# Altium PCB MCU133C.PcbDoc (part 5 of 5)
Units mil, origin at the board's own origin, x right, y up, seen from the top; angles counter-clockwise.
Board outline 2300 x 5500 mil, 4 copper layers (Top Signal, GND, PWR, Bottom Signal), stack 61.6 mil thick; 278 components, 226 nets, 1057 pads, 868 vias.
Unrouted connection lines stored in the file: 237.
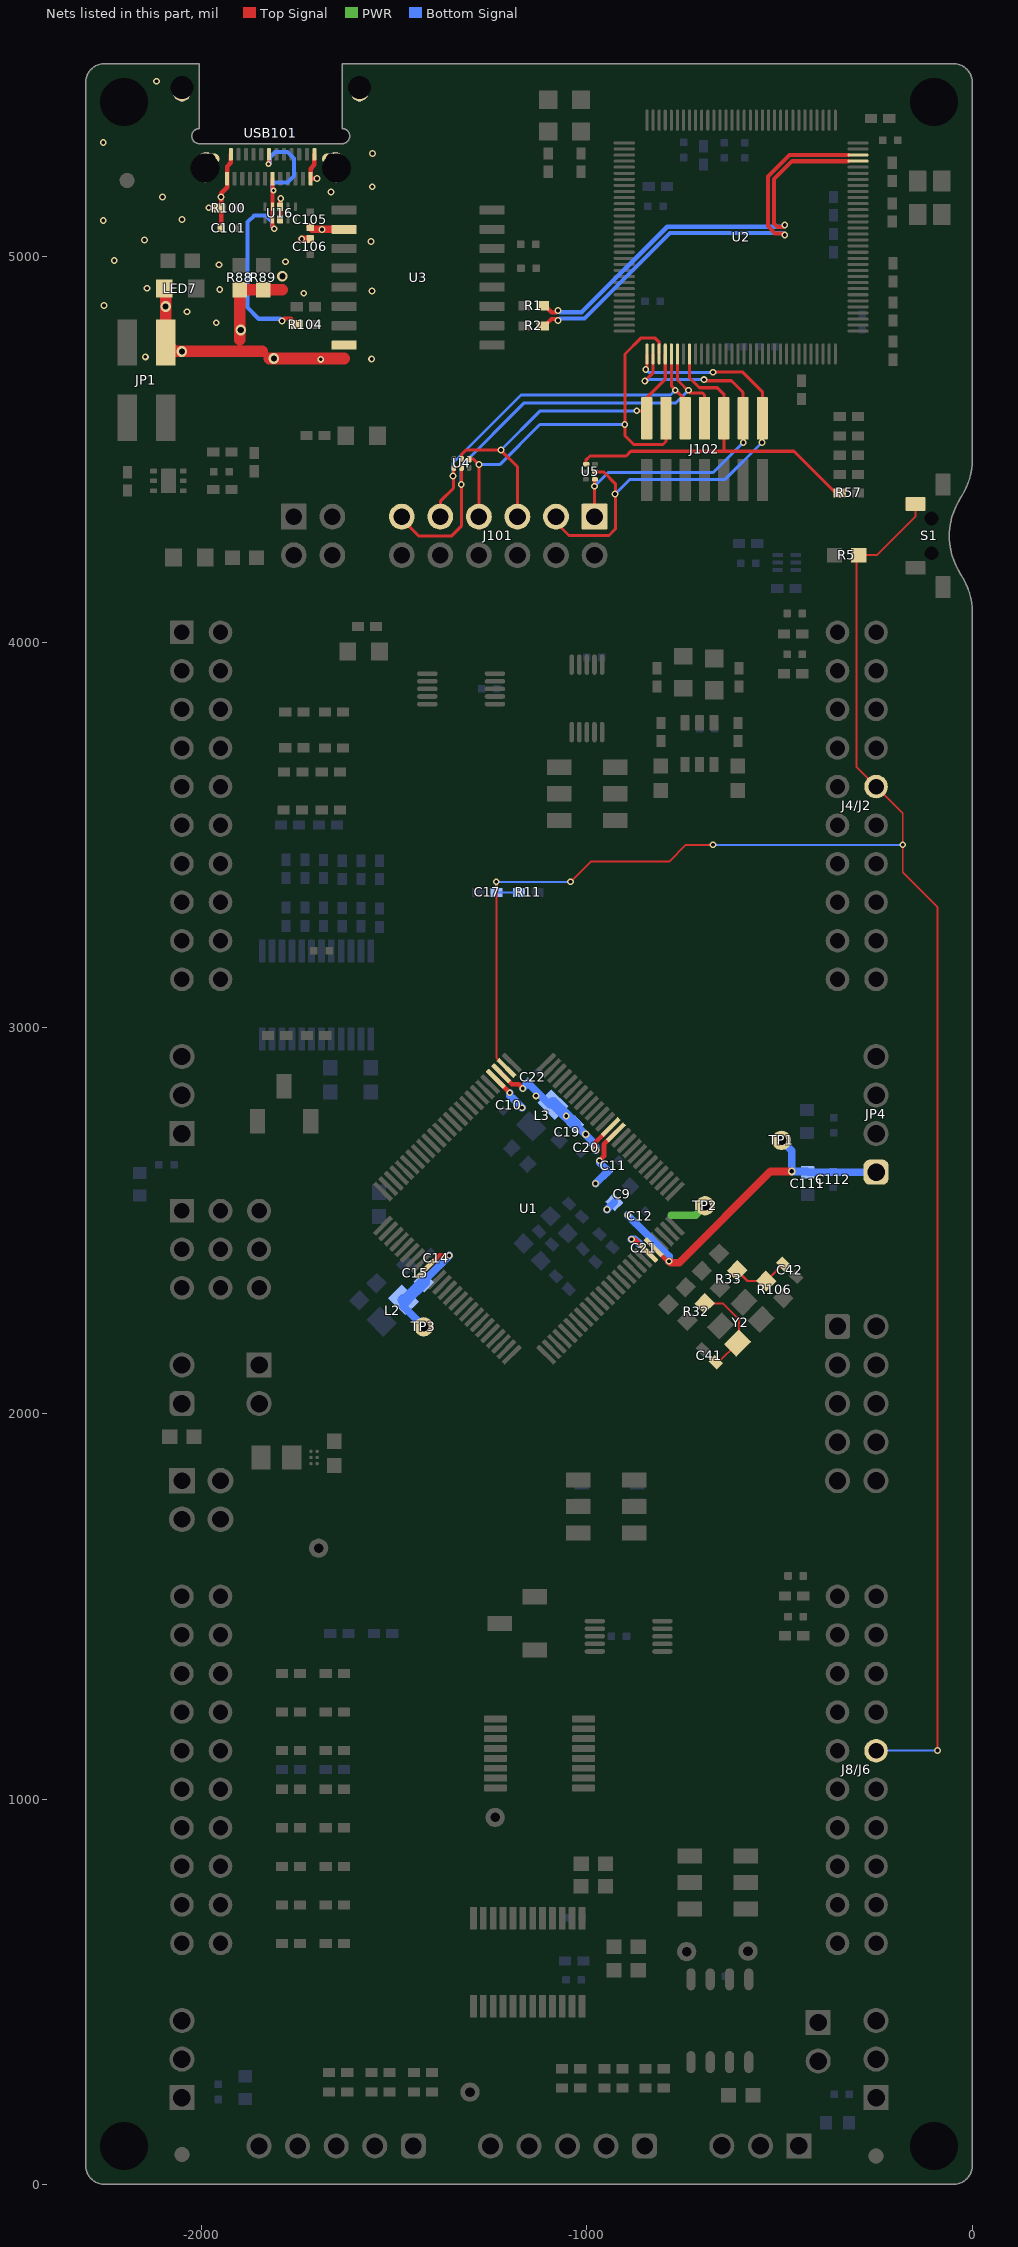
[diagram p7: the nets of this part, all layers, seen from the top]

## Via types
v1: diameter 17.72, hole 9.84, Top Signal to Bottom Signal, tented both sides, 822 vias
v2: diameter 19.68, hole 11.81, Top Signal to Bottom Signal, tented both sides, 22 vias
v3: diameter 27.56, hole 15.75, Top Signal to Bottom Signal, tented both sides, 17 vias
v4: diameter 15.75, hole 7.87, Top Signal to Bottom Signal, tented both sides, 5 vias
v5: diameter 19.68, hole 7.87, Top Signal to Bottom Signal, tented both sides, 2 vias

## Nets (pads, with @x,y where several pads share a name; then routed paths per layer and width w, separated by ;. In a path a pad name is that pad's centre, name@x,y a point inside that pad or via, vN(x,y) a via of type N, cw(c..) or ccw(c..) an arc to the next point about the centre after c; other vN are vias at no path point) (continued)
USB_D_P: R104.1 U16.2 U16.9 USB101.A6 USB101.B6 | length 849.1
  Top Signal w7.87: v4(-1825.43,5239.8) v4@-1824.65,5240.59
  Top Signal w10.63: v4@-1824.65,5240.59 USB101.B6@-1824.65,5265.12 ; USB101.A6@-1814.8,5202.13 -1814.8,5171.54 -1814.8,5076.3 v1(-1810.51,5072.01) ; v1(-1790.71,4833.23) -1784.86,4839.07 -1767.85,4839.07 R104.1@-1752.2,4823.43
  Bottom Signal w10.63: v4(-1825.43,5239.8) -1822.09,5243.15 -1822.09,5256.97 -1808.11,5270.94 -1776.18,5270.94 -1759.29,5254.05 -1759.29,5208.62 -1776.3,5191.61 -1808.94,5191.61 -1816.65,5183.9 -1816.65,5175.51 v4(-1812.68,5171.54) ; v1(-1810.51,5072.01) -1816.32,5077.82 -1816.32,5089.62 -1833.39,5106.69 -1862.44,5106.69 -1879.92,5089.21 -1879.92,4867.72 -1850.91,4838.7 -1796.18,4838.7 v1(-1790.71,4833.23)
USB_GND: C101.1 C105.1 C106.1 JP1.3 LED7.1 R88.1 R89.1 R100.1 U3.2 U3.8 U16.3@-1795.2,5096.4 U16.8@-1795.2,5129.27 USB101.1 USB101.2 USB101.3 USB101.4 USB101.A1 USB101.A12 USB101.B1 USB101.B12 | length 1317.6
  Top Signal w11.81: v1(-1980.55,5126.73) -1953.46,5126.73 R100.1@-1952.28,5125.55 ; C101.1@-1948.43,5073.35 -1948.43,5164.61 -1932.91,5180.12 USB101.A12@-1932.91,5202.13 -1932.91,5233.58 -1923.07,5243.43 USB101.B1@-1923.07,5265.12 ; U16.8@-1795.2,5132.38 -1794.37,5133.21 U16.8@-1795,5133.84 ; U16.3@-1795,5098.84 v1@-1795,5150.39 ; C106.1@-1718.24,5045.35 C106.1@-1716.04,5047.55 ; USB101.B12@-1706.54,5265.12 -1706.54,5237.99 -1716.38,5228.15 USB101.A1@-1716.38,5202.13 v1(-1699.41,5202.13)
  Top Signal w19.68: v1(-1739.31,5045.35) C106.1@-1718.24,5045.35 ; C105.1@-1717.44,5075.67 -1712.32,5070.55 U3.2@-1629.53,5070.55
  Top Signal w30: LED7.1@-2092.01,4919.41 JP1.3@-2092.01,4776.99 -2069.31,4754.29 -1930.04,4754.29 -1842.09,4754.29 ; -1899.66,4784.67 R88.1@-1899.66,4913.94 R89.1@-1838.7,4913.94 -1789.8,4913.94 ; v3@-1823.35,4735.55 -1629.53,4735.55
  other v1: -1690.16,4733.46 -1558.03,4734.49 -2144.92,4739.92 -1961.18,4828.27 -2037.01,4856.97 -2251.85,4873.07 -1734.21,4904.65 -1557.52,4910.67 -1952.01,4914.45 -2140.35,4917.8 -1954.29,4978.78 -1781.54,4986.55 -2225.55,4989.61 -1559.61,5039.13 -2147.32,5043.11 -1686.5,5069.88 -2254.17,5093.66 -2049.65,5095.94 -1793.58,5150.39 -2100.2,5154.57 -1948.9,5154.45 -1663.43,5167.76 -1556.46,5181.18 -1555.63,5267.17 -2254.17,5295.87 -2116.3,5454.41
  other v3: -1811.57,4735.47 -2050.2,4753.74 -1897.48,4809.45 -2092.17,4870.63 -1789.8,4948.94
VDD: C9.2 C10.2 C11.2 C12.2 C111.2 C112.2 JP4.1 TP1.1 U1.4 U1.71 U1.87 | length 1252.7
  Top Signal w11.81: U1.4@-1236.36,2867.95 -1200.04,2831.63 v1(-1200.04,2831.55) v1@-1202.6,2831.55 ; U1.71@-827.13,2430.88 -790.94,2394.69 v1(-787.04,2394.69)
  Top Signal w12: v1(-966.92,2655.21) -955.69,2666.44 -955.69,2697.63 U1.87@-924.56,2728.76
  Top Signal w19.68: v1(-787.04,2394.69) -782.82,2390.47 -760.81,2390.47 -523.8,2627.48 v2(-468.54,2627.48)
  Bottom Signal w19.68: v1(-1200.04,2831.55) -1200.04,2824.22 C10.2@-1188.79,2812.97 ; C10.2@-1188.71,2813.06 v1@-1168.12,2792.47 ; v1(-977.46,2596.32) C11.2@-945.16,2628.61 -966.92,2650.38 v1(-966.92,2655.21) ; v1(-947.83,2528.53) -947.83,2528.7 C9.2@-928.74,2547.79 ; v1@-893.94,2515.67 v1(-893.94,2514.28) C12.2@-876.54,2496.88 -787.04,2407.38 v1(-787.04,2394.69) ; TP1.1@-495.04,2708.05 -468.54,2681.56 v2(-468.54,2627.48) C111.2@-429.6,2627.48 ; C111.2@-427.54,2625.43 -427.41,2625.55 C112.2@-361.04,2625.55 JP4.1@-250.04,2625.55
  other v1: -1168.04,2792.55
VDDA: C14.2 C15.1 L2.2 TP3.1 U1.34 | length 334.2
  Top Signal w11.81: U1.34@-1417.31,2375.2 -1382.96,2409.55 v1(-1356.72,2409.55)
  Bottom Signal w19.68: L2.2@-1475.38,2294.55 -1475.38,2276.88 TP3.1@-1423.05,2224.55 ; C15.1@-1422.93,2340.95 -1422.93,2343.3 -1389.39,2376.85 v1(-1356.72,2409.55)
  Bottom Signal w31.5: L2.2@-1475.38,2294.55 -1469.34,2294.55 C15.1@-1422.93,2340.95
VDDIO: C19.2 C20.2 C21.2 C22.2 L3.2 TP2.1 U1.3 U1.70 U1.88 | length 610.2
  Top Signal w11.81: U1.3@-1222.44,2881.87 -1194.12,2853.55 -1176.69,2853.55 v1(-1166.04,2842.9) ; v1(-976.46,2682.79) -976.46,2704.7 U1.88@-938.48,2742.68 ; v1(-884.22,2451.55) -875.64,2451.55 U1.70@-841.05,2416.96
  PWR w19.68: -781.04,2513.53 -718.38,2513.53 -697.04,2534.87 TP2.1@-697.04,2544.55
  Bottom Signal w19.68: v1(-1166.04,2842.9) -1153.72,2855.22 C22.2@-1153.72,2858.05 -1096.5,2800.84 L3.2@-1087.75,2800.84 ; C19.2@-1030.23,2749.93 -987.69,2707.39 C20.2@-987.69,2702.47 -976.46,2691.24 v1(-976.46,2682.79) ; v1(-884.22,2451.55) -875.64,2451.55 C21.2@-865.96,2441.87
  Bottom Signal w30: L3.2@-1087.75,2806.06 v1(-1053.25,2771.55) C19.2@-1030.23,2749.93
  other v1: -1132.04,2823.55
  other v2: -1003.04,2723.55
XDS_D_N: R1.2 U2.93 | length 1103.7
  Top Signal w10.63: R1.2@-1114.29,4872.4 -1109.05,4872.4 -1091.08,4854.43 -1080.37,4854.43 v1(-1074.72,4860.08) ; v1@-485.08,5084.8 -493.07,5076.81 -505.43,5076.81 -514.21,5085.59 -514.21,5200.55 -467.5,5247.26 U2.93@-322.75,5247.26
  Bottom Signal w7.87: v1(-1074.72,4860.08) -1074.72,4857.84 -1073.5,4856.61 -1072.38,4857.74 v1@-1070.03,4860.08
  Bottom Signal w10.63: v1(-1074.72,4860.08) -1072.38,4857.74 -1070.17,4855.53 -1013.32,4855.53 -791.53,5077.32 -490.98,5077.32 v1(-486.65,5081.65)
XDS_D_P: R2.2 U2.94 | length 1149.7
  Top Signal w10.63: R2.2@-1114.29,4819.92 -1109.76,4819.92 -1091.79,4837.89 -1077.06,4837.89 v1@-1073.65,4834.49 ; v1@-484.29,5054.09 -490.47,5060.28 -512.28,5060.28 -530.75,5078.74 -530.75,5207.4 -474.35,5263.8 U2.94@-321.93,5263.8
  Bottom Signal w10.63: v1@-1073.65,4834.49 -1069.14,4839 -1006.48,4839 -784.68,5060.79 -491.38,5060.79 v1(-486.65,5056.06)
  other v1: -1074.72,4834.49
XDS_RESET_OUT: J102.10 R57.1 U2.40 U5.1 | length 1039.1
  Top Signal w5: R57.1@-355.24,4387.32 R57.1@-344.21,4387.32
  Top Signal w7.87: U5.1@-1001.77,4461.42 -1001.77,4473.11 -991.85,4483.03 -897.95,4483.03 -885.82,4495.16 -463.07,4495.16 R57.1@-355.24,4387.32 ; U2.40@-733.7,4747.4 -733.7,4685.39 -708.11,4659.8 -661.54,4659.8 -644.84,4643.11 J102.10@-644.84,4580.67 -644.84,4495.43
XDS_RXD: J101.3 J102.14 U2.33 U5.5 | length 1311.9
  Top Signal w5: J101.3@-1080.04,4311.02 J101.3@-1080.04,4325.55
  Top Signal w7.87: J101.3@-1080.04,4311.02 -1080.04,4310.51 -1046.34,4276.81 -942.83,4276.81 -926.14,4293.5 -926.14,4411.18 -956.69,4441.73 U5.5@-979.13,4441.73 ; v1@-850.79,4706.02 -843.94,4712.87 U2.33@-843.94,4747.4 ; v1@-673.19,4700.08 -595.75,4700.08 -544.84,4649.17 J102.14@-544.84,4580.67 -545.79,4579.72 v1(-545.79,4517.99)
  Bottom Signal w7.87: v1(-926.77,4383.98) -889.45,4421.3 -642.48,4421.3 v1(-545.79,4517.99) ; v1(-847.2,4707.2) -839.92,4699.92 v1(-673.19,4699.92)
XDS_TCK_SWDCLK: J101.7 J102.4 U2.35 U4.1 | length 1120.2
  Top Signal w7.87: U4.1@-1305.28,4474.57 -1294.17,4474.57 v1(-1280.04,4460.43) J101.7@-1280.04,4325.55 ; U2.35@-812.44,4747.4 -812.44,4778.11 -823.58,4789.25 -858.98,4789.25 -901.14,4747.09 -901.14,4535.08 -878.54,4512.48 -802.56,4512.48 -794.84,4520.2 J102.4@-794.84,4580.67
  Bottom Signal w7.87: v1(-1280.04,4460.43) -1225.98,4460.43 -1122.05,4564.37 v1(-901.69,4564.37)
XDS_TDI: J101.11 J102.8 U2.38 U4.5 | length 1272.2
  Top Signal w7.87: J101.11@-1480.04,4325.55 -1480.04,4319.92 -1435.12,4275 -1351.4,4275 -1325.56,4300.84 U4.5@-1325.56,4450.19 ; U2.38@-765.2,4747.4 -765.2,4679.96 -731.1,4645.87 -699.84,4645.87 -694.84,4640.87 J102.8@-694.84,4580.67
  Bottom Signal w7.87: v1(-1325.91,4408.66) -1325.91,4457.13 -1162.48,4620.55 -769.05,4620.55 v1(-736.38,4653.23)
XDS_TDO_SWO: J101.9 J102.6 U2.37 U4.4 | length 1008.2
  Top Signal w7.87: J101.9@-1380.04,4325.55 -1380.04,4365.16 -1345.87,4399.33 U4.4@-1345.87,4449.57 ; U2.37@-780.94,4747.4 -780.94,4665.12 -744.84,4629.02 J102.6@-744.84,4580.67
  Bottom Signal w7.87: v1(-1347.17,4430.67) -1347.17,4464.65 -1170.91,4640.9 -783.27,4640.9 v1(-770.94,4653.23)
XDS_TMS_SWDIO: J101.5 J102.2 U2.36 U4.2 | length 916.3
  Top Signal w7.87: U4.2@-1324.96,4475.55 -1324.96,4487.24 -1314.13,4498.07 -1223.54,4498.07 -1180.04,4454.57 J101.5@-1180.04,4325.55 ; v1(-870.63,4599.96) -847.99,4599.96 J102.2@-844.84,4603.11 ; J102.2@-844.84,4580.67 J102.2@-844.84,4603.11 ; U2.36@-796.69,4747.4 -796.69,4682.05 -844.84,4633.9 J102.2@-844.84,4603.11
  Bottom Signal w7.87: v1(-1222.87,4498.23) -1121.14,4599.96 v1(-870.63,4599.96)
XDS_TXD: J101.1 J102.12 U2.34 U5.4 | length 1004.7
  Top Signal w5: U5.4@-980.04,4418.66 U5.4@-974.65,4424.06
  Top Signal w7.87: J101.1@-980.04,4325.55 U5.4@-980.04,4418.66 ; v1(-849.65,4677.24) -828.19,4698.7 U2.34@-828.19,4747.4 ; v1@-697.99,4677.95 -624.88,4677.95 -594.84,4647.91 J102.12@-594.84,4580.67 -594.33,4580.16 v1(-594.33,4517.99)
  Bottom Signal w7.87: v1(-980.39,4404.41) -944.88,4439.92 -672.4,4439.92 v1(-594.33,4517.99) ; v1@-842.64,4680.75 v1(-696.54,4680.75)
XRSn: C17.1 J4/J2.16 J8/J6.56 R5.1 R11.1 S1.4 U1.2 | length 5280.9
  Top Signal w5: v1(-1234.78,3378.55) -1234.78,2922.05 U1.2@-1208.52,2895.79 ; v1(-1042.18,3378.55) -989.65,3431.08 -786.51,3431.08 -743.04,3474.55 v1(-673.09,3474.55) ; R5.1@-301.5,4224.45 -302.6,4225.55 R5.1@-294.72,4225.55 ; S1.4@-147.6,4358.23 -147.6,4326.24 -248.29,4225.55 R5.1@-294.72,4225.55 ; v1@-90.98,1125.26 -91.04,1125.31 -91.04,1697.33 -91.04,3313.32 -180.75,3403.03 -180.75,3556.26 J4/J2.16@-250.04,3625.55 -301.18,3676.69 -301.18,4219.09 R5.1@-294.72,4225.55
  Bottom Signal w5: R11.1@-1175.6,3350.95 C17.1@-1234.42,3350.95 -1234.78,3351.31 v1(-1234.78,3378.55) v1(-1042.18,3378.55) ; v1(-673.09,3474.55) v1(-180.68,3474.55) ; J8/J6.56@-250.04,1125.55 v1(-90.98,1125.55) ; J4/J2.16@-250.04,3598.07 J4/J2.16@-250.04,3625.55
XTAL_X1: C42.1 R33.2 R106.2 | length 165.2
  Top Signal w6: R33.2@-610.27,2354.22 R33.2@-610.27,2370.47 -583.42,2343.61 R106.2@-535.06,2343.61 -490.95,2387.73 C42.1@-490.74,2387.73
XTAL_X2: C41.1 R32.2 Y2.1 | length 246.5
  Top Signal w5: R32.2@-694.59,2285.48 -647.46,2285.48 -605.04,2243.06 -605.04,2186.62 Y2.1@-609.18,2182.48 -658.93,2132.73 C41.1@-665.7,2132.73
pads on no net: FID1.1 FID2.1 FID3.1 FID4.1 FID5.1 FID6.1 J11.9 J102.7 M1.0 M2.0 M3.0 M4.0 M5.0 M6.0 M7.0 M8.0 M9.0 M10.0 M11.0 M12.0 M13.0 MH1.1 MH2.1 MH3.1 MH4.1 S1. U1.37 U2.1 U2.2 U2.5 U2.6 U2.11 U2.12 U2.13 U2.14 U2.15 U2.18 U2.19 U2.20 U2.21 U2.22 U2.23 U2.24 U2.25 U2.27 U2.29 U2.30 U2.31 U2.32 U2.41 U2.42 U2.43 U2.44 U2.45 U2.46 U2.49 U2.50 U2.53 U2.54 U2.56 U2.57 U2.65 U2.67 U2.71 U2.72 U2.73 U2.74 U2.75 U2.76 U2.77 U2.78 U2.81 U2.82 U2.83 U2.84 U2.85 U2.86 U2.91 U2.92 U2.95 U2.97 U2.98 U2.99 U2.100 U2.102 U2.103 U2.104 U2.105 U2.106 U2.107 U2.108 U2.109 U2.110 U2.111 U2.112 U2.116 U2.117 U2.118 U2.119 U2.120 U2.121 U2.123 U2.124 U2.125 U2.126 U2.127 U2.128 U5.2 U10.6 U15.5 U15.8 U16.3@-1795.2,5096.4 U16.8@-1795.2,5129.27 U17.3 U101.5 U101.7@-2085.04,4400.55 U101.7@-2085.04,4435.98 USB101.A2 USB101.A3 USB101.A8 USB101.A10 USB101.A11 USB101.B2 USB101.B3 USB101.B8 USB101.B10 USB101.B11

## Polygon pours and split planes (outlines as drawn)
+3V3_XDS110 on PWR "PWR-+3V3_XDS110" (solid, remove dead copper, pour order 12): -1404.37,5475.06 -25.04,5475.06 -25.04,4290.51 -1705.35,4290.51 -1705.35,4620.55 -1466.54,4620.55 -1404.56,4682.53
+5V0_XDS110 on PWR "PWR_+5V0_XDS110_P042" (solid, remove dead copper, pour order 42): -2274.55,4620.55 -2274.55,4290.51 -1713.04,4290.51 -1713.04,4620.55
USB_GND on PWR "Top Signal-USB_GND" (solid, remove dead copper, pour order 49): -2304.96,4723.74 -1516.7,4723.74 -1502.99,4737.44 -1502.99,5502.8 -2263.35,5502.8 -2263.35,5499.88 -2304.96,5458.27
VDD on PWR "VDD" (solid, remove dead copper, pour order 61): -1223.44,2779.52 -918.36,2474.44 -911.83,2474.44 -870.06,2516.21 -1178.4,2824.56
VDDIO on PWR "VDDIO" (solid, remove dead copper, pour order 63): -1149.07,2814.02 -1149.01,2842.59 -1122.04,2869.55 -1085.04,2869.55 -795.87,2580.38 -795.87,2550.27 -828.59,2517.55 -852.6,2517.55 -886.6,2551.55
VDDIO on PWR "VDDIO" (solid, remove dead copper, pour order 65): -795.87,2580.38 -739.78,2524.29 -739.78,2488.82 -825.55,2403.04 -878.34,2403.04 -913.67,2438.38 -913.7,2461.09 -914.39,2461.78 -856.81,2519.36 -856.81,2566.7 -843.04,2580.47
+5V0_MCU on PWR "PWR_+5V0_MCU_P067" (solid, remove dead copper, pour order 67): -1726.37,4260.39 -2274.55,4260.39 -2274.55,16.04 -2275.04,15.55 -777.48,15.55 -777.48,531.78 -806.25,560.55 -2021.87,560.55 -2125.04,663.72 -2125.04,4041.78 -2071.38,4095.43 -1761.69,4095.43 -1726.37,4130.76
+3V3_MCU on PWR "PWR-+3V3_MCU" (solid, remove dead copper, pour order 69): -2100.39,4052.83 -2100.39,678.98 -2011.2,589.78 -794.71,579.43 -751.81,540.88 -751.81,26.02 -25.04,25.55 -25.04,584.09 -25.04,4260.39 -1705.85,4260.39 -1705.85,4118.64 -1767.76,4060.83 -2095.07,4060.83
USB_GND on Top Signal "Top Signal-USB_GND" (solid, remove dead copper, pour order 20): -2304.96,4723.74 -1516.7,4723.74 -1502.99,4737.44 -1502.99,5502.8 -2263.35,5502.8 -2263.35,5499.88 -2304.96,5458.27
GND on Top Signal "GND-GND" (solid, remove dead copper, pour order 71): -2300.91,4618.74 -1468.35,4618.74 -1402.01,4685.08 -1402.01,5502.2 -39.88,5502.2 0.55,5461.77 0.55,34.02 -33.43,0.04 -2263.74,0.04 -2300.31,36.61 -2300.31,4617.17 -2299.45,4618.03
GND on GND "GND-GND" (solid, remove dead copper, pour order 73): -2300.91,4618.74 -1468.35,4618.74 -1402.01,4685.08 -1402.01,5502.2 -39.88,5502.2 0.55,5461.77 0.55,34.02 -33.43,0.04 -2263.74,0.04 -2300.31,36.61 -2300.31,4617.17 -2299.45,4618.03
USB_GND on GND "Top Signal-USB_GND" (solid, remove dead copper, pour order 47): -2304.96,4723.74 -1516.7,4723.74 -1502.99,4737.44 -1502.99,5502.8 -2263.35,5502.8 -2263.35,5499.88 -2304.96,5458.27
USB_GND on Bottom Signal "Top Signal-USB_GND" (solid, remove dead copper, pour order 51): -2304.96,4723.74 -1516.7,4723.74 -1502.99,4737.44 -1502.99,5502.8 -2263.35,5502.8 -2263.35,5499.88 -2304.96,5458.27
GND on Bottom Signal "GND-GND" (solid, remove dead copper, pour order 75): -2300.91,4618.64 -1468.35,4618.65 -1402.01,4684.98 -1402.01,5502.11 -39.88,5502.11 0.55,5461.67 0.55,33.92 -33.43,-0.06 -2263.74,-0.06 -2300.31,36.52 -2300.31,4617.07 -2299.45,4617.93

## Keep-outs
Keep-Out Layer:
  lines w7.87: -2004.76,5500.55 -2250.04,5500.55 ccw(c-2250.04,5450.55) -2300.04,5450.55 -2300.04,50.55 ccw(c-2250.04,50.55) -2250.04,0.55 -50.04,0.55 ccw(c-50.04,50.55) -0.04,50.55 -0.04,4075.55 ccw(c-181.71,4075.55) -30.04,4175.55 cw(c121.63,4275.55) -30.04,4375.55 ccw(c-181.71,4475.55) -0.04,4475.55 -0.04,5450.55 ccw(c-50.04,5450.55) -50.04,5500.55 -1634.68,5500.55
  text ".Layer_Name" at -1708.09,-854.14 h60

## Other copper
Top Signal:
  pour cut-out: -902.99,5294.65 -902.99,4806.46 -843.94,4747.4 -355.75,4747.4 -296.69,4806.46 -296.69,5294.65 -355.75,5353.7 -843.94,5353.7
  pour cut-out: -456.93,1710.1 -446,1721.02 -446,1752.13 -491.67,1752.13 -494.53,1749.27 -474.45,1729.19 -474.45,1702.62
  pour cut-out: -1065.91,1795.91 -985.39,1795.91 -979.49,1790 -1065.91,1790
  pour cut-out: -631.18,820.98 -631.18,683.19 -526.4,683.19 -522.04,687.55 -531.76,697.27 -531.76,830.53 -621.63,830.53
  pour cut-out: -776.85,640.05 -767.47,630.66 -709.16,630.66 -690.24,649.59 -690.24,820.98 -773.65,820.98 -777.08,817.55 -776.85,817.32
  region net GND: -1694.72,1947.55 -1704.04,1938.23 -1704.04,1901.55 -1700.04,1897.55 -1611.04,1897.55 -1599.04,1909.55 -1599.04,1947.55
  pour cut-out: -1115.12,3575.37 -1115.12,3496.85 -882.83,3496.85 -882.83,3575.37
  region net +5V0_MCU: -1703.04,1890.55 -1703.04,1867.66 -1680.93,1845.55 -1663.24,1845.55 -1641.04,1867.76 -1641.04,1880.55 -1645.04,1884.55 -1683.04,1884.55 -1689.04,1890.55
  region net NetJ16_2: -1715.38,1870 -1730.04,1855.35 -1730.04,1819.55 -1710.04,1819.55 -1702.04,1827.55 -1702.04,1856.66
  region net NetL4_2: -1715.38,1885.75 -1740.18,1910.55 -1748.04,1910.55 -1748.04,1860.55 -1740.58,1860.55
  pour cut-out: -1290.23,5011.54 -1290.23,4795.99 -1248.07,4795.99 -1248.07,4804.66 -1248.07,5011.54 -1289.44,5011.54
  pour cut-out: -2041.97,4881.65 -2059.68,4881.65 -2059.68,4887.56 -2041.97,4887.56
  pour cut-out: -698.62,3982.32 -720.92,3982.49 -720.92,3993.43 -698.9,3993.43
  text ".Layer_Name" at -1727.91,-849.44 h60
GND:
  text ".Layer_Name" at -1655.28,-852.47 h60
PWR:
  text ".Layer_Name" at -1652.18,-847.93 h60
Bottom Signal:
  pour cut-out: -709.39,2215.32 -690.3,2196.22 -690.3,2173.58 -674.38,2173.58 -652.53,2195.43 -659.78,2202.69 -659.78,2221.81 -696.69,2221.81 -700.14,2218.37
  pour cut-out: -1082.16,2546.41 -1086.04,2542.53 -1086.04,2526.74 -1037.85,2478.55 -1020.04,2496.36 -1020.04,2498.55 -1067.9,2546.41
  pour cut-out: -1475.29,2233.38 -1470.78,2237.89 -1470.78,2245.55 -1488.78,2263.55 -1496.04,2263.55 -1504.04,2255.55 -1504.04,2253.49 -1483.93,2233.38
  region net GND: -917.32,2623.24 -886.01,2654.55 -855.04,2654.55 -855.04,2634.14 -850.04,2629.14 -850.04,2612.16 -869.65,2592.55 -906.83,2592.55 -917.32,2603.04
  region net VDDIO: -1118.68,2796.38 -1142.04,2819.75 -1142.04,2831.55 -1128.98,2844.61 -1099.04,2814.66 -1099.04,2800.05 -1103.54,2795.55
  text ".Layer_Name" at -1716.36,-852.05 h60

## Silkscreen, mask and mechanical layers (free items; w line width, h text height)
Top Overlay:
  drawing of 13411 lines, arcs and shapes, not listed
  text "XDS110 Out" at -824.84,4660.55 h51.18
  text "+5V0" at -2275.04,4610.55 h51.18 r270
  text "GND" at -2049.5,4609.56 h51.18 r270
  text "XRSn" at -187.44,4455.22 h72.83
  text "+5V0" at -1768.54,4172.6 h45 r270
  text "+3V3" at -1668.53,4172.6 h51.18 r270
  text "TDO" at -1394.72,4162.09 h51.18 r270
  text "TDI" at -1494.72,4160.55 h51.18 r270
  text "TCK" at -1297.91,4160.55 h51.18 r270
  text "TMS" at -1196.69,4160.55 h51.18 r270
  text "TXD<<" at -1094.19,4159.94 h51.18 r270
  text "RXD>>" at -992.84,4157.89 h51.18 r270
  text "IO.0" at -534.88,4157.89 h51.18
  text "IO.1" at -534.88,4120.33 h51.18
  text "B11/D16" at -2263.74,3912.3 h51.18
  text "IO.57" at -185.54,3910.98 h51.18
  text "A6" at -1891.73,3825.55 h51.18
  text "IO.32" at -185.54,3815.55 h51.18
  text "IO.28" at -2213.44,3810.55 h51.18
  text "IO.2" at -486.32,3810.55 h51.18
  text "D14" at -1891.73,3790.79 h51.18
  text "B2" at -1893.79,3725.55 h51.18
  text "1" at -896.55,3717.55 h51.18
  text "1" at -1136.32,3713.17 h51.18
  text "IO.3" at -485.75,3710.55 h51.18
  text "IO.31" at -185.54,3710.55 h51.18
  text "C6" at -1895.04,3685.55 h51.18
  text "IO.29" at -2213.2,3660.55 h51.18
  text "A11" at -1895.04,3626.28 h51.18
  text "IO.10" at -509.54,3610.55 h51.18
  text "XRSn" at -185.54,3610.55 h51.18
  text "B10" at -1892.04,3590.79 h51.18
  text "SEL1" at -1125,3546.05 h51.18 r90
  text "SEL2" at -849.67,3544.05 h51.18 r90
  text "A14" at -1897.04,3527.86 h51.18
  text "A7/B30" at -2246.04,3510.55 h51.18
  text "IO.11" at -507.84,3510.55 h51.18
  text "IO.8" at -185.54,3510.55 h51.18
  text "B14" at -1893.04,3492.36 h51.18
  text "0" at -1142.04,3468.65 h51.18
  text "0" at -893.94,3465.55 h51.18
  text "A2" at -1895.04,3426.74 h51.18
  text "IO.9" at -2190.07,3411.65 h51.18
  text "IO.22" at -508.88,3410.55 h51.18
  text "IO.17" at -185.54,3410.55 h51.18
  text "B6" at -1891.04,3392.06 h51.18
  text "SEL1:" at -1239.87,3350.37 h51.18
  text "IO28," at -1062.55,3350.37 h51.18
  text "IO15," at -882.18,3350.37 h51.18
  text "IO.24" at -2213.87,3310.55 h51.18
  text "IO.23" at -509.73,3310.55 h51.18
  text "IO.21" at -185.54,3310.55 h51.18
  text "B3" at -1894.33,3308.05 h51.18
  text "SEL2" at -1239.87,3300.37 h51.18
  text "IO29" at -1062.55,3300.37 h51.18
  text "IO56" at -882.18,3300.37 h51.18
  text ":" at -1171.55,3239.87 h51.18
  text "0" at -1206.55,3235.87 h51.18
  text "0" at -1152.93,3235.87 h51.18
  text "XDS" at -1038.18,3235.87 h51.18
  text "BP" at -844.89,3235.87 h51.18
  text "C1" at -1895.04,3225.55 h51.18
  text "IO.51" at -2211.55,3210.55 h51.18
  text "IO.4" at -510.15,3210.55 h51.18
  text "IO.47" at -185.54,3210.55 h51.18
  text "E11" at -1894.04,3190.55 h51.18
  text ":" at -1170.69,3177.37 h51.18
  text "0" at -1205.69,3173.37 h51.18
  text "1" at -1145.69,3173.37 h51.18
  text "XDS" at -1038.18,3173.37 h51.18
  text "NC" at -844.89,3173.37 h51.18
  text "A1" at -1895.04,3120.55 h51.18
  text ":" at -1170.47,3115.37 h51.18
  text "1" at -1200.47,3111.37 h51.18
  text "0" at -1151.84,3111.37 h51.18
  text "BP" at -1016.18,3111.37 h51.18
  text "BP" at -844.89,3111.37 h51.18
  text "IO.34" at -2213.87,3110.55 h51.18
  text "IO.5" at -509.54,3110.55 h51.18
  text "IO.48" at -185.54,3110.55 h51.18
  text "B7" at -1891.04,3085.55 h51.18
  text ":" at -1170.11,3053.95 h51.18
  text "1" at -1200.11,3049.95 h51.18
  text "1" at -1145.11,3049.95 h51.18
  text "BP" at -1016.18,3049.95 h51.18
  text "XDS" at -861.43,3049.95 h51.18
  text "PGA Select" at -1903.78,2892.71 h51.18
  text "0" at -1662.62,2859.32 h51.18
  text "1" at -1925.04,2857.15 h51.18
  text "VDD" at -613.05,2737.76 h51.18
  text "BP" at -1929.71,2673.08 h51.18
  text "J10" at -1707.04,2673.08 h51.18
  text "1" at -2037.64,2580.87 h62.99
  text "2" at -1961.36,2580.47 h62.99
  text "3" at -1860.68,2580.47 h62.99
  text "VDDIO" at -646.97,2539.63 h51.18
  text "PGA_P" at -2307.22,2495.24 h62.99
  text "*" at -693.73,2464.98 h25
  text "PGA_N" at -2288.04,2384.55 h62.99
  text "*" at -857.13,2323.12 h25
  text "FSI" at -367.64,2277.87 h51.18
  text "TXCLK" at -190.04,2200.55 h51.18
  text "RXCLK" at -580.85,2152.32 h51.18
  text "VDDA" at -1477.04,2135.79 h51.18
  text "VREFHI" at -1751.54,2112.71 h51.18
  text "ENABLE" at -2266.95,2097.19 h51.18
  text "+5V0" at -2216.58,2059.06 h51.18
  text "BOOST" at -2248.88,2018.75 h51.18
  text "TXD0" at -190.04,2000.55 h51.18
  text "RXD0" at -545.04,1990.55 h51.18
  text "LAUNCHXL- / F28P55X" at -1384.02,1930.59 h50 r0.23
  text "RXD1" at -525.04,1895.55 h51.18
  text "TXD1" at -190.04,1895.55 h51.18
  text "1" at -849.88,1867.55 h51.18
  text "1" at -1072.83,1860.49 h51.18
  text "GND" at -211.32,1703.65 h51.18
  text "+5V0 / TO / J7" at -1871,1693.26 h51.18
  text "+3V3 / TO / J5" at -2257.54,1692.95 h51.18
  text "GPIO24" at -1090.57,1672.15 h51.18 r90
  text "GPIO32" at -781.97,1672.15 h51.18 r90
  text "IO.12" at -552.74,1652.2 h51.18
  text "GND" at -1658.04,1639.55 h51.18
  text "IO.13" at -551.24,1615.75 h51.18
  text "0" at -1073.5,1607.4 h51.18
  text "BOOT" at -1004.88,1603.5 h51.18
  text "0" at -854.88,1603.5 h51.18
  text "BP" at -1084.16,1514.55 h51.18
  text "Q3" at -1330.07,1441.05 h51.18
  text "IO.27" at -190.54,1410.55 h51.18
  text "C14" at -2184.54,1409.8 h51.18
  text "J13" at -1090.66,1357.55 h51.18
  text "B0" at -1894.42,1325.55 h51.18
  text "IO.15" at -2213.94,1310.55 h51.18
  text "IO.25" at -190.54,1310.55 h51.18
  text "IO.6" at -485.68,1305.55 h51.18
  text "C11" at -1893.5,1291 h51.18
  text "QEP Select" at -1304.4,1277.95 h51.18
  text "A10" at -1895.01,1227.52 h51.18
  text "IO.30" at -190.54,1210.55 h51.18
  text "IO.7" at -485.53,1200.55 h51.18
  text "B1" at -1891.01,1191.55 h51.18
  text "IO.56" at -2214.75,1160.55 h51.18
  text "A5" at -1892.01,1110.55 h51.18
  text "IO.37" at -508.81,1110.55 h51.18
  text "XRSn" at -190.54,1110.55 h51.18
  text "A4" at -1894.01,1028.11 h51.18
  text "A9" at -2160.21,1010.55 h51.18
  text "IO.35" at -508,1010.55 h51.18
  text "IO.60" at -190.54,1010.55 h51.18
  text "B8" at -1892.01,993.55 h51.18
  text "CAN" at -703.39,954.41 h51.18
  text "+3V3" at -1387.83,931.55 h51.18
  text "B4" at -1892.01,924.62 h51.18
  text "ROUTE" at -723.39,915.28 h51.18
  text "IO.62" at -506.77,915.55 h51.18
  text "IO.14" at -2214.6,910.55 h51.18
  text "IO.61" at -190.54,910.55 h51.18
  text "C8" at -1895.01,889.19 h51.18
  text "BP" at -829.21,835.55 h51.18
  text "B5" at -1892.01,821.38 h51.18
  text "IO.55" at -2216.04,811.57 h51.18
  text "IO.20" at -190.54,810.55 h51.18
  text "IO.63" at -506.77,805.55 h51.18
  text "D15" at -1893.25,786.67 h51.18
  text "A12" at -1894.01,727.83 h51.18
  text "*" at -2239.81,716.38 h25
  text "IO.18" at -2214.6,710.55 h51.18
  text "IO.58" at -506.77,710.55 h51.18
  text "IO.26" at -190.54,710.55 h51.18
  text "XCVR" at -881,700.5 h51.18
  text "C5" at -1892.01,691.55 h51.18
  text "A0" at -1896.01,627.35 h51.18
  text "*" at -2239.81,616.03 h25
  text "IO.19" at -2214.37,610.55 h51.18
  text "IO.16" at -190.54,610.55 h51.18
  text "IO.33" at -508.47,605.55 h51.18
  text "B15" at -1892.01,592.55 h51.18
  text "+5V0" at -1259.5,228.49 h51.18
  text "CAN" at -540.04,170.55 h51.18
  text "EQEP3" at -1714.44,167.52 h51.18
  text "EQEP1" at -1116.56,167.52 h51.18
  text "GND" at -1890.04,10.55 h51.18
  text "5V" at -1775.04,10.55 h51.18
  text "3I" at -1671.42,10.55 h51.18
  text "3B" at -1575.04,10.55 h51.18
  text "3A" at -1475.04,10.55 h51.18
  text "GND" at -1290.04,10.55 h51.18
  text "5V" at -1175.04,10.55 h51.18
  text "1I" at -1065.79,10.55 h51.18
  text "1B" at -970.04,10.55 h51.18
  text "1A" at -870.04,10.55 h51.18
  text "GND" at -690.04,10.55 h51.18
  text "LO" at -575.04,10.55 h51.18
  text "HI" at -470.04,10.55 h51.18
  text ".Layer_Name" at -1725.11,-851.21 h60
Bottom Overlay:
  drawing of 12861 lines, arcs and shapes, not listed
  text "LAUNCHXL-F28P55X / Development Kit" at -0.04,5321.42 h100
  text "www.ti.com/launchpad" at -0.04,4525.55 h100
  text "J3/J1" at -1930.45,4097.22 h66.93
  text "J2/J4" at -231.79,4094.69 h66.93
  text "40" at -417.04,4010.55 h51.18
  text "39" at -417.32,3914.65 h51.18
  text "2" at -2117.04,3910.55 h51.18
  text "19" at -138.04,3910.55 h51.18
  text "38" at -417.04,3815.55 h51.18
  text "3" at -2117.04,3810.55 h51.18
  text "23" at -1833.04,3810.55 h51.18
  text "18" at -138.04,3810.55 h51.18
  text "4" at -2117.04,3710.55 h51.18
  text "24" at -1833.04,3710.55 h51.18
  text "37" at -417.04,3710.55 h51.18
  text "17" at -138.04,3710.55 h51.18
  text "5" at -2117.04,3610.55 h51.18
  text "25" at -1833.04,3610.55 h51.18
  text "36" at -417.04,3610.55 h51.18
  text "16" at -138.04,3610.55 h51.18
  text "6" at -2117.04,3510.55 h51.18
  text "26" at -1833.04,3510.55 h51.18
  text "35" at -417.04,3510.55 h51.18
  text "15" at -138.04,3510.55 h51.18
  text "7" at -2117.04,3410.55 h51.18
  text "27" at -1833.04,3410.55 h51.18
  text "34" at -417.04,3410.55 h51.18
  text "14" at -138.04,3410.55 h51.18
  text "8" at -2117.04,3310.55 h51.18
  text "28" at -1833.04,3310.55 h51.18
  text "33" at -417.04,3310.55 h51.18
  text "13" at -138.04,3310.55 h51.18
  text "29" at -1835.37,3266.1 h51.18
  text "9" at -2117.04,3210.55 h51.18
  text "32" at -417.04,3210.55 h51.18
  text "12" at -138.04,3210.55 h51.18
  text "10" at -2117.04,3110.55 h51.18
  text "31" at -417.04,3110.55 h51.18
  text "11" at -148.04,3110.55 h51.18
  text "30" at -1914.7,3025.26 h51.18
  text "'.PRJ_Number'.PCB_Rev" at -942.52,1900.55 h108.27
  text "J6/J8" at -227.73,1599.45 h66.93
  text "J7/J5" at -1929.58,1598.53 h66.93
  text "80" at -417.04,1515.55 h51.18
  text "42" at -2117.04,1410.55 h51.18
  text "79" at -417.04,1410.55 h51.18
  text "59" at -133.04,1410.1 h51.18
  text "43" at -2117.04,1310.55 h51.18
  text "63" at -1833.04,1310.55 h51.18
  text "78" at -417.04,1310.55 h51.18
  text "58" at -133.04,1310.1 h51.18
  text "44" at -2117.04,1210.55 h51.18
  text "64" at -1833.04,1210.55 h51.18
  text "77" at -417.04,1210.55 h51.18
  text "57" at -133.04,1210.1 h51.18
  text "45" at -2117.04,1110.55 h51.18
  text "65" at -1833.04,1110.55 h51.18
  text "76" at -417.04,1110.55 h51.18
  text "56" at -133.04,1110.1 h51.18
  text "46" at -2117.04,1010.55 h51.18
  text "66" at -1833.04,1010.55 h51.18
  text "75" at -417.04,1010.55 h51.18
  text "55" at -133.04,1010.1 h51.18
  text "47" at -2117.04,910.55 h51.18
  text "67" at -1833.04,910.55 h51.18
  text "74" at -417.04,910.55 h51.18
  text "54" at -133.04,910.1 h51.18
  text "48" at -2117.04,810.55 h51.18
  text "68" at -1833.04,810.55 h51.18
  text "73" at -417.04,810.55 h51.18
  text "53" at -133.04,810.1 h51.18
  text "49" at -2117.04,710.55 h51.18
  text "69" at -1833.04,710.55 h51.18
  text "72" at -417.04,710.55 h51.18
  text "52" at -133.04,710.1 h51.18
  text "TP8" at -714.04,638.94 h45
  text "TP7" at -542.46,638.94 h45
  text "50" at -2117.04,610.55 h51.18
  text "70" at -1833.04,610.55 h51.18
  text "71" at -417.04,610.55 h51.18
  text "51" at -143.04,610.55 h51.18
  text "CANRX" at -714.04,540.88 h45
  text "CANTX" at -504.1,540.88 h45
  text "For evaluation only; not FCC approved for resale." at -550.04,149.23 h60
  text "GND" at -1810.04,15.55 h51.18
  text "5V" at -1725.04,15.55 h51.18
  text "3I" at -1625.04,15.55 h51.18
  text "3B" at -1525.04,15.55 h51.18
  text "3A" at -1425.04,15.55 h51.18
  text "GND" at -1210.04,15.55 h51.18
  text "5V" at -1125.04,15.55 h51.18
  text "1I" at -1033.4,15.55 h51.18
  text "1B" at -930.04,15.55 h51.18
  text "1A" at -830.04,15.55 h51.18
  text ".Layer_Name" at -1708.36,-851.32 h60
Top Paste:
  text ".Layer_Name" at -1721.2,-862.06 h60
Bottom Paste:
  text ".Layer_Name" at -1716.58,-857.39 h60
Top Solder:
  text ".Layer_Name" at -1726.04,-862.94 h60
Bottom Solder:
  text ".Layer_Name" at -1712.04,-856.94 h60
Drill Guide:
  text ".Layer_Name" at -1716.04,-856.94 h60
M1 Board Outline:
  lines w10: -2004.76,5500.55 -2250.04,5500.55 ccw(c-2250.04,5450.55) -2300.04,5450.55 -2300.04,50.55 ccw(c-2250.04,50.55) -2250.04,0.55 -50.04,0.55 ccw(c-50.04,50.55) -0.04,50.55 -0.04,4075.55 ccw(c-181.71,4075.55) -30.04,4175.55 cw(c121.63,4275.55) -30.04,4375.55 ccw(c-181.71,4475.55) -0.04,4475.55 -0.04,5450.55 ccw(c-50.04,5450.55) -50.04,5500.55 -1634.69,5500.55
  text ".Layer_Name" at -1724.9,-857.74 h60
M2 Board Dimensions:
  text ".Layer_Name" at -1718.92,-859.36 h60
M3 3D STEP Top:
  text ".Layer_Name" at -1726.04,-853.94 h60
M4 3D STEP Bottom:
  text ".Layer_Name" at -1724.84,-855.98 h60
M5 Assembly Top:
  lines w10: -2591.54,-926.11 4008.46,-926.11 ; -2591.54,-722.78 4010.46,-722.78 ; -2591.54,-519.45 -2591.54,-1129.45 1413.46,-1129.45 4010.46,-1129.45 4010.46,-519.45 -2591.04,-519.45 -2591.04,-1129.45 -1015.54,-1129.45 ; -126.54,-1129.45 -126.54,-519.45 ; 1140.46,-722.78 1140.46,-519.45 ; 1980.46,-722.78 1980.46,-519.45 ; 2602.46,-1135.95 2602.46,-933.11
  text "COMPONENTS MARKED 'DNP' SHOULD NOT BE POPULATED." at -1146.04,-314.45 h60
  text "ASSEMBLY VARIANT:" at -1146.54,-429.95 h60
  text ".VariantName" at -110.54,-429.95 h60
  text "PCB VIEWED FROM TOP SIDE" at -2528.04,-651.62 h60
  text "BOARD #:" at -51.54,-651.62 h60
  text ".PRJ_Number" at 493.96,-651.62 h60
  text "REV:" at 1338.46,-651.62 h60
  text ".PCB_Rev" at 1629.96,-651.62 h60
  text "SVN REV:" at 2176.46,-651.62 h60
  text ".VersionControl_RevNumber" at 2682.46,-651.62 h60
  text ".Layer_Name" at -1719.54,-855.95 h60
  text "TID #:" at -51.54,-854.95 h60
  text ".TID" at 493.96,-854.95 h60
  text "PLOT NAME =" at -2528.04,-1060.28 h60
  text ".plot_File_Name" at -1722.54,-1060.28 h60
  text "GENERATED    :" at -49.54,-1060.28 h60
  text ".Print_Date" at 819.96,-1060.28 h60
  text ".Print_Time" at 1548.96,-1060.28 h60
  text "TEXAS INSTRUMENTS" at 2813.46,-1060.28 h60
M6 Assembly Bottom:
  lines w10: -2591.04,-723.78 4010.96,-723.78 ; -2589.04,-927.11 4010.96,-927.11 ; -1183.04,-1136.95 -1183.04,-934.11 ; -561.04,-723.78 -561.04,-520.45 ; 278.96,-723.78 278.96,-520.45 ; 1545.96,-1130.45 1545.96,-520.45 ; 2434.96,-1130.45 4010.46,-1130.45 4010.46,-520.45 -2591.04,-520.45 -2591.04,-1130.45 5.96,-1130.45 4010.96,-1130.45 4010.96,-520.45
  text "COMPONENTS MARKED 'DNP' SHOULD NOT BE POPULATED." at 3803.46,-314.45 h60
  text ".VariantName" at 2759.46,-430.45 h60
  text "ASSEMBLY VARIANT:" at 3798.46,-430.45 h60
  text ".VersionControl_RevNumber" at -1263.04,-652.62 h60
  text "SVN REV:" at -757.04,-652.62 h60
  text ".PCB_Rev" at -210.54,-652.62 h60
  text "REV:" at 80.96,-652.62 h60
  text ".PRJ_Number" at 925.46,-652.62 h60
  text "BOARD #:" at 1470.96,-652.62 h60
  text "PCB VIEWED FROM BOTTOM SIDE" at 3947.46,-652.62 h60
  text ".Layer_Name" at -1718.54,-856.45 h60
  text ".TID" at 925.46,-855.95 h60
  text "TID #:" at 1470.96,-855.95 h60
  text "TEXAS INSTRUMENTS" at -1394.04,-1061.28 h60
  text ".Print_Time" at -129.54,-1061.28 h60
  text ".Print_Date" at 599.46,-1061.28 h60
  text "GENERATED    :" at 1468.96,-1061.28 h60
  text ".plot_File_Name" at 3141.96,-1061.28 h60
  text "PLOT NAME =" at 3947.46,-1061.28 h60
M7 LPKF Text Top:
  text ".Layer_Name" at -1718.54,-852.25 h60
M8 LPKF Text Bottom:
  text ".Layer_Name" at -1717.9,-857.48 h60
M9 Title Sheet:
  drawing of 57 lines, arcs and shapes, not listed
  text "1" at -1560.2,8037.05 h70
  text "2" at 935.46,8037.05 h70
  text "3" at 3424.8,8037.05 h70
  text "4" at 5931.47,8037.05 h70
  text "5" at 8430.46,8037.05 h70
  text "6" at 10935.46,8037.05 h70
  text "A" at -2716.54,6894.05 h70
  text "A" at 12083.46,6894.05 h70
  text "B" at -2716.54,4514.05 h70
  text "B" at 12083.46,4514.05 h70
  text "C" at -2716.54,2139.05 h70
  text "C" at 12083.46,2139.05 h70
  text "PROJECT TITLE:" at 9043.46,278.05 h45
  text ".PRJ_Title" at 9093.46,144.72 h70
  text "DESIGNED FOR:" at 9043.46,-22.95 h45
  text ".PRJ_Customer" at 9093.46,-162.95 h70
  text "D" at -2716.54,-230.95 h70
  text "D" at 12083.46,-230.95 h70
  text "FILE NAME:" at 9043.46,-322.95 h45
  text ".PCB_File_Name_No_Path" at 9093.46,-442.95 h70
  text "Texas Instruments (TI) and/or its licensors do not warrant the accuracy or completeness of this specification" at 4073.96,-604.79 h45
  text "ENGINEER:" at 9043.46,-612.95 h45
  text "LAYOUT BY:" at 10548.46,-612.95 h45
  text "or any information contained therein. TI and/or its licensors do not warrant that this design will meet" at 4028.98,-717.45 h45
  text ".PRJ_Engineer" at 9093.46,-767.94 h70
  text ".PCB_Layout" at 10598.96,-767.94 h70
  text "the specifications, will be suitable for your application or fit for any particular purpose, or will operate in" at 4028.98,-830.12 h45
  text ".Layer_Name" at -1723.04,-857.94 h60
  text "ALTIUM DESIGNER VERSION:" at 10548.46,-922.95 h45
  text "an implementation. TI and/or its licensors do not warrant that the design is production worthy. You should" at 4028.98,-942.78 h45
  text "completely validate and test your design implementation to confirm the system functionality for your application." at 4073.96,-1055.45 h45
  text ".print_Scale" at 9093.46,-1056.28 h70
  text ".Application_BuildNumber" at 10598.96,-1056.28 h70
  text "1" at -1560.2,-1262.95 h70
  text "2" at 935.46,-1262.95 h70
  text "3" at 3424.8,-1262.95 h70
  text "4" at 5931.47,-1262.95 h70
  text "5" at 8430.46,-1262.95 h70
  text "6" at 10935.46,-1262.95 h70
M10 Fab Notes:
  drawing of 189 lines, arcs and shapes, not listed
  text "DESIGN INFORMATION" at 10083.98,6363.73 h60
  text "MIN. TRACK WIDTH:" at 9439.42,6231.6 h60
  text "5" at 10535.66,6231.6 h60
  text "MIL" at 10690.42,6231.6 h60
  text "0.15" at 10434.96,6115.55 h60
  text "MIN. CLEARANCE:" at 9439.42,6107.47 h60
  text "mm" at 10690.42,6107.47 h60
  text "MIN. VIA PAD SIZE:" at 9439.42,5983.35 h60
  text "0.45" at 10434.96,5983.35 h60
  text "mm" at 10690.42,5983.35 h60
  text "0.05mm (2MIL)" at 10134.42,5853.45 h60
  text "MINIMUM ANNULAR RING" at 9110.19,5845.23 h60
  text "EXTERNAL" at 10842.42,5845.23 h60
  text "PER" at 9310.19,5735.1 h60
  text "IPC-D-275 CLASS 2 LEVEL C" at 9530.19,5735.1 h60
  text "MIL, HOLES" at 11018.42,5634.62 h60
  text "+/-" at 10625.96,5626.03 h60
  text "+/-" at 11479.96,5626.03 h60
  text "REGISTRATION TOLERANCES:" at 9110.19,5624.97 h60
  text "METAL" at 10309.96,5624.97 h60
  text "5" at 10886.16,5624.97 h60
  text "3" at 11719.16,5624.97 h60
  text "MIL" at 11835.42,5624.97 h60
  text "HOLE SIZE TOLERANCE (UNLESS OTHERWISE SPECIFIED):" at 9110.19,5526.65 h60
  text "+/-" at 11479.96,5523.78 h60
  text "5" at 11719.16,5522.72 h60
  text "MIL" at 11835.42,5522.72 h60
  text "MATERIAL:" at 9035.42,5385.07 h60
  text "FR-4 High Tg" at 10021.86,5256.55 h60
  text "X" at 9877.42,5248.56 h60
  text "FR-408" at 9456.42,5244.04 h60
  text "OTHER" at 10944.42,5244.04 h60
  text "62 MIL (1.6mm) +/-10%" at 9776.52,5101.01 h60
  text "X" at 9656.42,5098.56 h60
  text "THICKNESS:" at 9110.19,5092.79 h60
  text "OTHER" at 11061.42,5092.79 h60
  text "TOLERANCE:" at 9110.19,4954.47 h60
  text "ANSI IPC-6012 TYPE 3 CLASS 2" at 10136.44,4954.47 h60
  text "IPC-A600" at 10821.96,4827.55 h72.83
  text "OTHER +/-" at 10136.42,4810.28 h60
  text "X" at 9966.96,4807.55 h60
  text "BOW & TWIST:" at 9110.19,4665.1 h60
  text "ANSI IPC-6012 TYPE 3 CLASS 2" at 10136.44,4665.1 h60
  text "X" at 9956.96,4542.55 h60
  text "IPC-A600" at 10821.96,4522.55 h72.83
  text "OTHER +/-" at 10136.42,4518.4 h60
  text "DRILLING:" at 9035.42,4387.78 h60
  text "NC_DRILL FILES" at 10796.42,4282.59 h60
  text "REFERENCE:" at 9110.19,4278.65 h60
  text "X" at 9767.42,4278.56 h60
  text "AS SHOWN" at 9945.42,4278.65 h60
  text "X" at 10668.42,4278.65 h60
  text "OTHER" at 11094.42,4136.4 h60
  text "PTH COPPER THICKNESS:" at 9109.87,4132.87 h60
  text "X" at 10249.1,4132.87 h60
  text "20-30 um" at 10377.1,4132.87 h60
  text "BOARD FINISH:" at 9035.42,3985.28 h60
  text "SILKSCREEN:" at 9190.64,3875.15 h60
  text "X" at 10148.42,3875.15 h60
  text "TOP" at 10265.42,3875.15 h60
  text "X" at 10658.42,3875.15 h60
  text "BOTTOM" at 10776.42,3875.15 h60
  text "SILKSCREEN COLOR:" at 9190.64,3719.96 h60
  text "X" at 10147.42,3719.96 h60
  text "WHITE" at 10265.42,3719.96 h60
  text "OTHER" at 10776.42,3719.96 h60
  text "RED" at 11413.96,3586.55 h80
  text "GREEN" at 10396.42,3576.51 h60
  text "OTHER" at 11014.42,3576.51 h60
  text "X" at 10867.96,3572.55 h60
  text "SOLDER RESIST COLOR:" at 9190.64,3569.65 h60
  text "MATTE" at 10396.42,3422.26 h60
  text "SEMI-GLOSS" at 11013.96,3421.62 h60
  text "IMMERSION GOLD (ENIG)" at 10096.42,3249.49 h60
  text "ENEPIG" at 11433.96,3242.27 h60
  text "SURFACE FINISH:" at 9035.42,3241.27 h60
  text "IMM. TIN/SILVER OR EQUIV" at 9364.96,3103.95 h60
  text "X" at 9216.96,3102.55 h60
  text "OTHER" at 10796.42,3100.02 h60
  text "ARRAY/PANEL:" at 9035.42,2944.64 h60
  text "CUT AND TRIM PER M1 BOARD OUTLINE" at 10096.42,2936.42 h60
  text "X" at 9917.96,2934.55 h60
  text "N.C. ROUTE" at 10096.42,2800.45 h60
  text "V. SCORE" at 10962.42,2800.45 h60
  text "CERTIFICATION:" at 9035.42,2671.32 h60
  text "MATERIALS AND WORKMANSHIP FOR ALL PCBS" at 9760.42,2671.32 h60
  text "TO MEET OR EXCEED THE REQUIREMENTS OF:" at 9760.42,2577.26 h60
  text "X" at 11174.93,2450.95 h60
  text "X" at 9397.93,2448.63 h60
  text "ANSI IPC-A-600F CLASS ->" at 9525.92,2448.63 h60
  text "2" at 11283.92,2448.63 h60
  text "1" at 10968.92,2447.13 h60
  text "3" at 11637.92,2447.13 h60
  text "X" at 10209.93,2300.95 h60
  text "RoHS" at 10337.92,2300.95 h60
  text "OTHER" at 10982.33,2300.95 h60
  text "PER ORDER" at 11379.38,2300.95 h60
  text "ALL BOARDS MUST MEET OR EXCEED UL94-V0 REQUIREMENTS." at 9062.96,2147.12 h60
  text "PCB MUST BEAR THE UL94V-0 UL REGISTERED MATERIAL ID NUMBER" at 9062.96,2031.06 h60
  text "ADDITIONAL REQUIREMENTS:" at 9035.42,1861.63 h60
  text "MICROSECTION:" at 9110.19,1754.5 h60
  text "YES" at 10015.92,1754.5 h60
  text "X" at 10293.96,1612.55 h60
  text "REQUIRED" at 10877.42,1610.17 h60
  text "BARE BOARD ELEC. TEST:" at 9110.19,1607.32 h60
  text "NONE" at 10415.92,1607.32 h60
  text "PER ORDER" at 11469.42,1607.32 h60
  text "XX MIL VIAS REQUIRE NON-CONDUCTIVE FILL AND PLANARIZE" at 9278.34,1402.37 h59
  text "XX MIL VIAS REQUIRE CONDUCTIVE FILL AND PLANARIZE" at 9286.34,1298.39 h60
  text "OUTER XX MIL VIAS REQUIRE 50 OHM SINGLE-ENDED IMPEDANCE" at 9285.35,1135.01 h58
  text "LAYER 2 & 3 (INNER LAYERS) XX MIL WIDE, XX MIL SPACE / TRACES REQUIRE 100 OHM DIFFERENTIAL IMPEDANCE" at 9277.35,899.3 h60
  text ".Layer_Name" at -1712.16,-856.82 h60
M12 Stackup:
  drawing of 295 lines, arcs and shapes, not listed
  text "Use Standard 4 Layer Stackup" at 4706.2,6006.04 h250
  text "Layer" at 4189.7,5747.55 h60
  text "Name" at 4599.61,5747.55 h60
  text "Material" at 5529.36,5747.55 h60
  text "Thickness" at 6389.13,5747.55 h60
  text "Constant" at 7038.96,5747.55 h60
  text "Board Layer Stack" at 7608.82,5747.55 h60
  text "Top Overlay" at 4599.61,5627.55 h60
  text "Top Solder" at 4599.61,5507.55 h60
  text "Solder Resist" at 5529.36,5507.55 h60
  text "0.40mil" at 6389.13,5507.55 h60
  text "3.5" at 7038.96,5507.55 h60
  text "1" at 4189.7,5387.55 h60
  text "Top Signal" at 4599.61,5387.55 h60
  text "1.40mil" at 6389.13,5387.55 h60
  text "Dielectric 1" at 4599.61,5267.55 h60
  text "FR-4" at 5529.36,5267.55 h60
  text "8.00mil" at 6389.13,5267.55 h60
  text "4.2" at 7038.96,5267.55 h60
  text "2" at 4189.7,5147.55 h60
  text "GND" at 4599.61,5147.55 h60
  text "1.40mil" at 6389.13,5147.55 h60
  text "Dielectric 2" at 4599.61,5027.55 h60
  text "FR-4" at 5529.36,5027.55 h60
  text "40.00mil" at 6389.13,5027.55 h60
  text "4.2" at 7038.96,5027.55 h60
  text "3" at 4189.7,4907.55 h60
  text "PWR" at 4599.61,4907.55 h60
  text "1.40mil" at 6389.13,4907.55 h60
  text "Dielectric 3" at 4599.61,4787.55 h60
  text "FR-4" at 5529.36,4787.55 h60
  text "8.00mil" at 6389.13,4787.55 h60
  text "4.2" at 7038.96,4787.55 h60
  text "4" at 4189.7,4667.55 h60
  text "Bottom Signal" at 4599.61,4667.55 h60
  text "1.40mil" at 6389.13,4667.55 h60
  text "Bottom Solder" at 4599.61,4547.55 h60
  text "Solder Resist" at 5529.36,4547.55 h60
  text "0.40mil" at 6389.13,4547.55 h60
  text "3.5" at 7038.96,4547.55 h60
  text "Bottom Overlay" at 4599.61,4427.55 h60
  text ".Layer_Name" at -1726.04,-859.94 h60
M13 Component Bodies Top:
  text ".Layer_Name" at -1717.09,-855.17 h60
M14 Component Bodies Bottom:
  text ".Layer_Name" at -1724.63,-849.21 h60
M15 Courtyards Top:
  text ".Layer_Name" at -1715.85,-850.17 h60
M16 Courtyards Bottom:
  text ".Layer_Name" at -1719.48,-851.43 h60
Drill Drawing:
  drawing of 184 lines, arcs and shapes, not listed
  text "Symbol" at 5283.38,3943.22 h72
  text "Quantity" at 5583.95,3943.22 h72
  text "Finished Hole Size" at 5915.95,3943.22 h72
  text "Plated" at 6552.51,3943.22 h72
  text "Hole Type" at 6811.65,3943.22 h72
  text "Drill Layer Pair" at 7186.81,3943.22 h72
  text "Hole Tolerance" at 7942.5,3943.22 h72
  text "2" at 5583.95,3818.9 h60
  text "35.43mil (0.900mm)" at 5915.95,3818.9 h60
  text "NPTH" at 6552.51,3818.9 h60
  text "Round" at 6811.65,3818.9 h60
  text "Top Signal - Bottom Signal" at 7186.81,3818.9 h60
  text "4" at 5583.95,3694.58 h60
  text "125.00mil (3.175mm)" at 5915.95,3694.58 h60
  text "NPTH" at 6552.51,3694.58 h60
  text "Round" at 6811.65,3694.58 h60
  text "Top Signal - Bottom Signal" at 7186.81,3694.58 h60
  text "7" at 5583.95,3570.26 h60
  text "7.87mil (0.200mm)" at 5915.95,3570.26 h60
  text "PTH" at 6552.51,3570.26 h60
  text "Round" at 6811.65,3570.26 h60
  text "Top Signal - Bottom Signal" at 7186.81,3570.26 h60
  text "325" at 5583.95,3445.94 h60
  text "9.84mil (0.250mm)" at 5915.95,3445.94 h60
  text "PTH" at 6552.51,3445.94 h60
  text "Round" at 6811.65,3445.94 h60
  text "Top Signal - Bottom Signal" at 7186.81,3445.94 h60
  text "+0.00mil" at 7942.5,3445.94 h60
  text "497" at 5583.95,3321.62 h60
  text "9.84mil (0.250mm)" at 5915.95,3321.62 h60
  text "PTH" at 6552.51,3321.62 h60
  text "Round" at 6811.65,3321.62 h60
  text "Top Signal - Bottom Signal" at 7186.81,3321.62 h60
  text "1" at 5583.95,3197.3 h60
  text "11.81mil (0.300mm)" at 5915.95,3197.3 h60
  text "PTH" at 6552.51,3197.3 h60
  text "Round" at 6811.65,3197.3 h60
  text "Top Signal - Bottom Signal" at 7186.81,3197.3 h60
  text "A" at 5258.1,3187.31 h55.25
  text "21" at 5583.95,3072.98 h60
  text "11.81mil (0.300mm)" at 5915.95,3072.98 h60
  text "PTH" at 6552.51,3072.98 h60
  text "Round" at 6811.65,3072.98 h60
  text "Top Signal - Bottom Signal" at 7186.81,3072.98 h60
  text "+0.00mil" at 7942.5,3072.98 h60
  text "16" at 5583.95,2948.66 h60
  text "15.75mil (0.400mm)" at 5915.95,2948.66 h60
  text "PTH" at 6552.51,2948.66 h60
  text "Round" at 6811.65,2948.66 h60
  text "Top Signal - Bottom Signal" at 7186.81,2948.66 h60
  text "1" at 5583.95,2824.34 h60
  text "15.75mil (0.400mm)" at 5915.95,2824.34 h60
  text "PTH" at 6552.51,2824.34 h60
  text "Round" at 6811.65,2824.34 h60
  text "Top Signal - Bottom Signal" at 7186.81,2824.34 h60
  text "+0.00mil" at 7942.5,2824.34 h60
  text "B" at 5258.1,2814.35 h55.25
  text "8" at 5583.95,2700.02 h60
  text "25.00mil (0.635mm)" at 5915.95,2700.02 h60
  text "PTH" at 6552.51,2700.02 h60
  text "Round" at 6811.65,2700.02 h60
  text "Top Signal - Bottom Signal" at 7186.81,2700.02 h60
  text "89" at 5583.95,2575.7 h60
  text "40.16mil (1.020mm)" at 5915.95,2575.7 h60
  text "PTH" at 6552.51,2575.7 h60
  text "Round" at 6811.65,2575.7 h60
  text "Top Signal - Bottom Signal" at 7186.81,2575.7 h60
  text "10" at 5583.95,2451.38 h60
  text "43.31mil (1.100mm)" at 5915.95,2451.38 h60
  text "PTH" at 6552.51,2451.38 h60
  text "Round" at 6811.65,2451.38 h60
  text "Top Signal - Bottom Signal" at 7186.81,2451.38 h60
  text "+/-1.97mil" at 7942.5,2451.38 h60
  text "20" at 5583.95,2327.06 h60
  text "43.31mil (1.100mm)" at 5915.95,2327.06 h60
  text "PTH" at 6552.51,2327.06 h60
  text "Round" at 6811.65,2327.06 h60
  text "Top Signal - Bottom Signal" at 7186.81,2327.06 h60
  text "32" at 5583.95,2202.74 h60
  text "45.28mil (1.150mm)" at 5915.95,2202.74 h60
  text "PTH" at 6552.51,2202.74 h60
  text "Round" at 6811.65,2202.74 h60
  text "Top Signal - Bottom Signal" at 7186.81,2202.74 h60
  text "2" at 5583.95,2078.42 h60
  text "27.56mil (0.700mm)" at 5915.95,2078.42 h60
  text "PTH" at 6552.51,2078.42 h60
  text "Slot" at 6811.65,2078.42 h60
  text "Top Signal - Bottom Signal" at 7186.81,2078.42 h60
  text "2" at 5583.95,1954.1 h60
  text "59.06mil (1.500mm)" at 5915.95,1954.1 h60
  text "PTH" at 6552.51,1954.1 h60
  text "Slot" at 6811.65,1954.1 h60
  text "Top Signal - Bottom Signal" at 7186.81,1954.1 h60
  text "2" at 5583.95,1829.78 h60
  text "74.80mil (1.900mm)" at 5915.95,1829.78 h60
  text "PTH" at 6552.51,1829.78 h60
  text "Slot" at 6811.65,1829.78 h60
  text "Top Signal - Bottom Signal" at 7186.81,1829.78 h60
  text "1039 Total" at 5583.95,1705.46 h60
  text "Slot definitions :" at 5283.38,1618.44 h60
  text "Routed Path Length" at 5734.1,1618.44 h60
  text "= Calculated from tool start centre position to tool end centre position." at 6273.84,1618.44 h60
  text "Hole Length" at 5734.1,1568.71 h60
  text "= Routed Path Length + Tool Size = Slot length as defined in the PCB layout" at 6074.04,1568.71 h60
  text ".Layer_Name" at -1706.84,-852.25 h60
Mechanical 17:
  text ".Layer_Name" at -1714.02,-856.21 h60
Mechanical 18:
  text ".Layer_Name" at -1712.04,-858.94 h60
Mechanical 19:
  text ".Layer_Name" at -1711.88,-851.43 h60

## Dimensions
-2300.04,0.55 to -2300.04,5500.55 on M2 Board Dimensions
-2300.04,0.55 to -0.04,0.55 on M2 Board Dimensions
